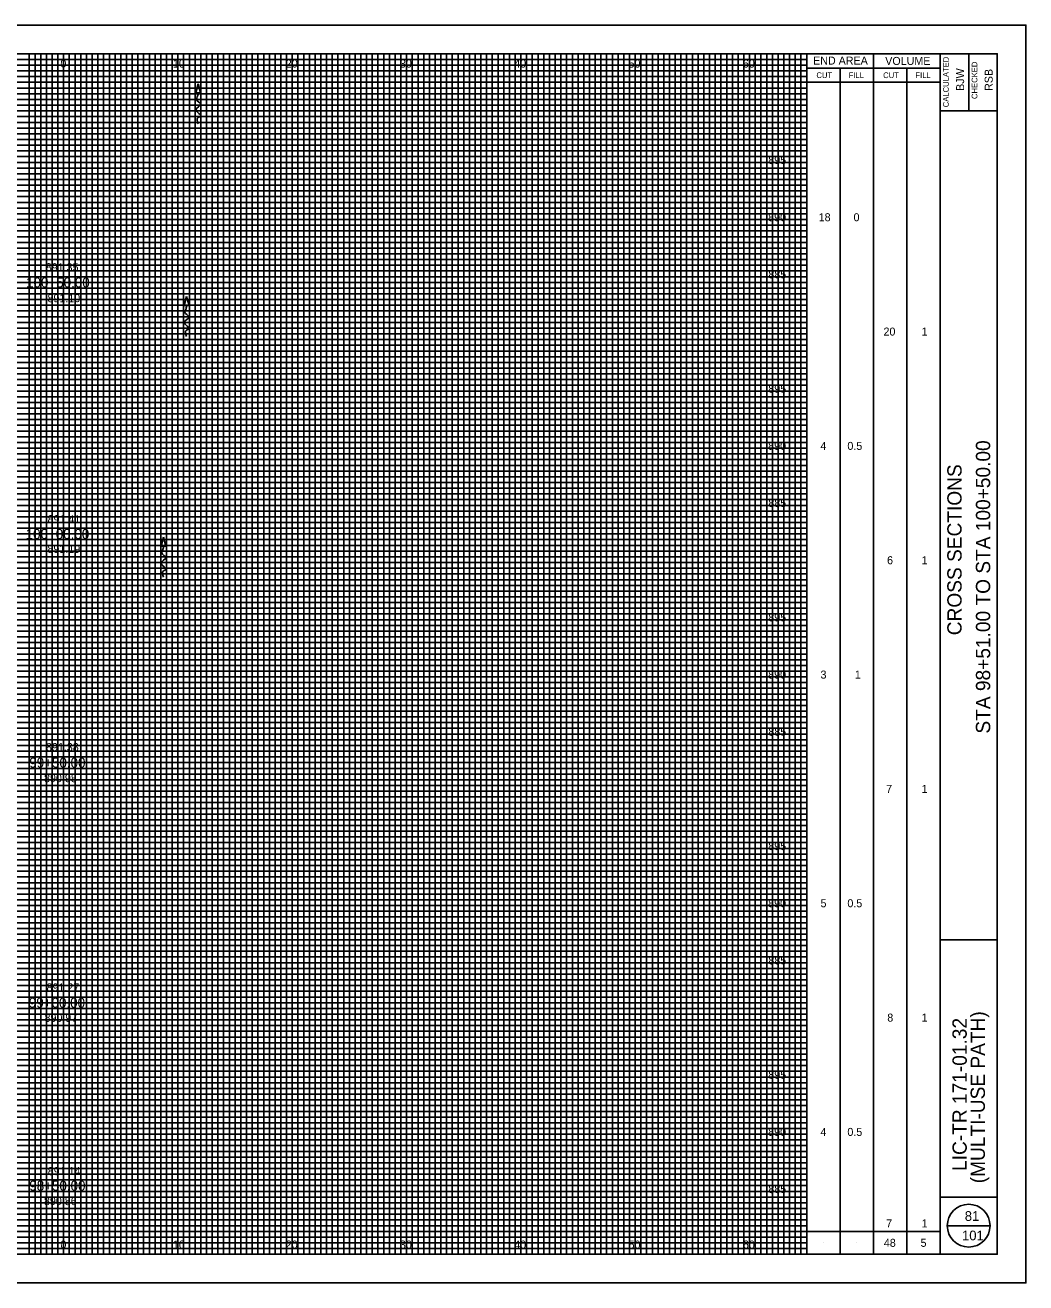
# Model space of a CAD drawing. Extents: x -10 to 160, y -2 to 3672.
# Drawn here: x 72.5 to 160, y 1377.5 to 1487.5 of the extents above; entities that cross this region are included whole.
import ezdxf

# ---------------------------------------------------------------- set-up
doc = ezdxf.new("R2010")
doc.units = 0
for name, color, linetype in [('DR_P_Flow_Arrow', 7, 'Continuous'), ('SH_Border', 7, 'Continuous'), ('SH_Cut_Line', 7, 'Continuous'), ('SH_Data', 7, 'Continuous'), ('SH_Major_Grid_Line', 7, 'Continuous'), ('SH_Minor_Grid_Line', 7, 'Continuous'), ('SH_Text', 7, 'Continuous'), ('TX_P_10', 7, 'Continuous'), ('TX_X_10', 7, 'Continuous')]:
    doc.layers.add(name, color=color, linetype=linetype)

msp = doc.modelspace()

# ---------------------------------------------------------------- linework, layer by layer
at = {"layer": 'DR_P_Flow_Arrow'}
for p, q in [((87.39, 1481.58), (87.6, 1482.38)), ((87.6, 1482.38), (87.81, 1481.58)), ((87.81, 1481.58), (87.39, 1481.58)), ((86.37, 1462.98), (86.58, 1463.78)), ((86.58, 1463.78), (86.8, 1462.98)), ((86.8, 1462.98), (86.37, 1462.98)), ((84.35, 1441.92), (84.56, 1442.72)), ((84.56, 1442.72), (84.78, 1441.92)), ((84.78, 1441.92), (84.35, 1441.92))]:
    msp.add_line(p, q, dxfattribs=at)
for points in [[(87.6, 1481.58), (87.6, 1481.55), (87.52, 1481.22), (87.45, 1481.01), (87.82, 1480.58), (87.41, 1480.1), (87.82, 1479.54), (87.59, 1479.43), (87.6, 1478.88)], [(86.58, 1462.98), (86.58, 1462.95), (86.51, 1462.62), (86.43, 1462.41), (86.8, 1461.99), (86.39, 1461.5), (86.8, 1460.94), (86.58, 1460.83), (86.58, 1460.28)], [(84.56, 1441.92), (84.56, 1441.89), (84.49, 1441.56), (84.41, 1441.35), (84.78, 1440.93), (84.37, 1440.44), (84.78, 1439.88), (84.56, 1439.77), (84.56, 1439.22)]]:
    msp.add_spline(points, degree=3, dxfattribs=at)
at = {"layer": 'SH_Border'}
for p, q in [((152.5, 1380), (152.5, 1485)), ((155, 1485), (155, 1480)), ((152.5, 1480), (157.5, 1480)), ((152.5, 1407.5), (157.5, 1407.5)), ((152.5, 1385), (157.5, 1385))]:
    msp.add_line(p, q, dxfattribs=at)
msp.add_lwpolyline([(0, 1485), (157.5, 1485), (157.5, 1380), (0, 1380)], close=True, dxfattribs=at)
at = {"layer": 'SH_Cut_Line'}
msp.add_lwpolyline([(-10, 1377.5), (160, 1377.5), (160, 1487.5), (-10, 1487.5)], close=True, dxfattribs=at)
at = {"layer": 'SH_Data'}
for p, q in [((140.83, 1380), (140.83, 1485)), ((146.67, 1380), (146.67, 1485)), ((140.83, 1483.75), (152.5, 1483.75)), ((143.75, 1380), (143.75, 1483.75)), ((149.58, 1380), (149.58, 1483.75)), ((140.83, 1482.5), (152.5, 1482.5)), ((140.83, 1382), (152.5, 1382)), ((153.12, 1382.5), (156.88, 1382.5)), ((142.29, 1381), (142.29, 1381)), ((145.21, 1381), (145.21, 1381)), ((148.12, 1381), (148.12, 1381)), ((151.04, 1381), (151.04, 1381))]:
    msp.add_line(p, q, dxfattribs=at)
msp.add_circle((155, 1382.5), 1.87, dxfattribs=at)
at = {"layer": 'SH_Major_Grid_Line'}
for p, q in [((75.83, 1380), (75.83, 1485)), ((80.83, 1380), (80.83, 1485)), ((85.83, 1380), (85.83, 1485)), ((90.83, 1380), (90.83, 1485)), ((95.83, 1380), (95.83, 1485)), ((100.83, 1380), (100.83, 1485)), ((105.83, 1380), (105.83, 1485)), ((110.83, 1380), (110.83, 1485)), ((115.83, 1380), (115.83, 1485)), ((120.83, 1380), (120.83, 1485)), ((125.83, 1380), (125.83, 1485)), ((130.83, 1380), (130.83, 1485)), ((135.83, 1380), (135.83, 1485)), ((5.83, 1480), (140.83, 1480)), ((5.83, 1475), (140.83, 1475)), ((5.83, 1470), (140.83, 1470)), ((5.83, 1465), (140.83, 1465)), ((5.83, 1460), (140.83, 1460)), ((5.83, 1455), (140.83, 1455)), ((5.83, 1450), (140.83, 1450)), ((5.83, 1445), (140.83, 1445)), ((5.83, 1440), (140.83, 1440)), ((5.83, 1435), (140.83, 1435)), ((5.83, 1430), (140.83, 1430)), ((5.83, 1425), (140.83, 1425)), ((5.83, 1420), (140.83, 1420)), ((5.83, 1415), (140.83, 1415)), ((5.83, 1410), (140.83, 1410)), ((5.83, 1405), (140.83, 1405)), ((5.83, 1400), (140.83, 1400)), ((5.83, 1395), (140.83, 1395)), ((5.83, 1390), (140.83, 1390)), ((5.83, 1385), (140.83, 1385))]:
    msp.add_line(p, q, dxfattribs=at)
at = {"layer": 'SH_Minor_Grid_Line'}
for p, q in [((72.83, 1380), (72.83, 1485)), ((73.33, 1380), (73.33, 1485)), ((73.83, 1380), (73.83, 1485)), ((74.33, 1380), (74.33, 1485)), ((74.83, 1380), (74.83, 1485)), ((75.33, 1380), (75.33, 1485)), ((76.33, 1380), (76.33, 1485)), ((76.83, 1380), (76.83, 1485)), ((77.33, 1380), (77.33, 1485)), ((77.83, 1380), (77.83, 1485)), ((78.33, 1380), (78.33, 1485)), ((78.83, 1380), (78.83, 1485)), ((79.33, 1380), (79.33, 1485)), ((79.83, 1380), (79.83, 1485)), ((80.33, 1380), (80.33, 1485)), ((81.33, 1380), (81.33, 1485)), ((81.83, 1380), (81.83, 1485)), ((82.33, 1380), (82.33, 1485)), ((82.83, 1380), (82.83, 1485)), ((83.33, 1380), (83.33, 1485)), ((83.83, 1380), (83.83, 1485)), ((84.33, 1380), (84.33, 1485)), ((84.83, 1380), (84.83, 1485)), ((85.33, 1380), (85.33, 1485)), ((86.33, 1380), (86.33, 1485)), ((86.83, 1380), (86.83, 1485)), ((87.33, 1380), (87.33, 1485)), ((87.83, 1380), (87.83, 1485)), ((88.33, 1380), (88.33, 1485)), ((88.83, 1380), (88.83, 1485)), ((89.33, 1380), (89.33, 1485)), ((89.83, 1380), (89.83, 1485)), ((90.33, 1380), (90.33, 1485)), ((91.33, 1380), (91.33, 1485)), ((91.83, 1380), (91.83, 1485)), ((92.33, 1380), (92.33, 1485)), ((92.83, 1380), (92.83, 1485)), ((93.33, 1380), (93.33, 1485)), ((93.83, 1380), (93.83, 1485)), ((94.33, 1380), (94.33, 1485)), ((94.83, 1380), (94.83, 1485)), ((95.33, 1380), (95.33, 1485)), ((96.33, 1380), (96.33, 1485)), ((96.83, 1380), (96.83, 1485)), ((97.33, 1380), (97.33, 1485)), ((97.83, 1380), (97.83, 1485)), ((98.33, 1380), (98.33, 1485)), ((98.83, 1380), (98.83, 1485)), ((99.33, 1380), (99.33, 1485)), ((99.83, 1380), (99.83, 1485)), ((100.33, 1380), (100.33, 1485)), ((101.33, 1380), (101.33, 1485)), ((101.83, 1380), (101.83, 1485)), ((102.33, 1380), (102.33, 1485)), ((102.83, 1380), (102.83, 1485)), ((103.33, 1380), (103.33, 1485)), ((103.83, 1380), (103.83, 1485)), ((104.33, 1380), (104.33, 1485)), ((104.83, 1380), (104.83, 1485)), ((105.33, 1380), (105.33, 1485)), ((106.33, 1380), (106.33, 1485)), ((106.83, 1380), (106.83, 1485)), ((107.33, 1380), (107.33, 1485)), ((107.83, 1380), (107.83, 1485)), ((108.33, 1380), (108.33, 1485)), ((108.83, 1380), (108.83, 1485)), ((109.33, 1380), (109.33, 1485)), ((109.83, 1380), (109.83, 1485)), ((110.33, 1380), (110.33, 1485)), ((111.33, 1380), (111.33, 1485)), ((111.83, 1380), (111.83, 1485)), ((112.33, 1380), (112.33, 1485)), ((112.83, 1380), (112.83, 1485)), ((113.33, 1380), (113.33, 1485)), ((113.83, 1380), (113.83, 1485)), ((114.33, 1380), (114.33, 1485)), ((114.83, 1380), (114.83, 1485)), ((115.33, 1380), (115.33, 1485)), ((116.33, 1380), (116.33, 1485)), ((116.83, 1380), (116.83, 1485)), ((117.33, 1380), (117.33, 1485)), ((117.83, 1380), (117.83, 1485)), ((118.33, 1380), (118.33, 1485)), ((118.83, 1380), (118.83, 1485)), ((119.33, 1380), (119.33, 1485)), ((119.83, 1380), (119.83, 1485)), ((120.33, 1380), (120.33, 1485)), ((121.33, 1380), (121.33, 1485)), ((121.83, 1380), (121.83, 1485)), ((122.33, 1380), (122.33, 1485)), ((122.83, 1380), (122.83, 1485)), ((123.33, 1380), (123.33, 1485)), ((123.83, 1380), (123.83, 1485)), ((124.33, 1380), (124.33, 1485)), ((124.83, 1380), (124.83, 1485)), ((125.33, 1380), (125.33, 1485)), ((126.33, 1380), (126.33, 1485)), ((126.83, 1380), (126.83, 1485)), ((127.33, 1380), (127.33, 1485)), ((127.83, 1380), (127.83, 1485)), ((128.33, 1380), (128.33, 1485)), ((128.83, 1380), (128.83, 1485)), ((129.33, 1380), (129.33, 1485)), ((129.83, 1380), (129.83, 1485)), ((130.33, 1380), (130.33, 1485)), ((131.33, 1380), (131.33, 1485)), ((131.83, 1380), (131.83, 1485)), ((132.33, 1380), (132.33, 1485)), ((132.83, 1380), (132.83, 1485)), ((133.33, 1380), (133.33, 1485)), ((133.83, 1380), (133.83, 1485)), ((134.33, 1380), (134.33, 1485)), ((134.83, 1380), (134.83, 1485)), ((135.33, 1380), (135.33, 1485)), ((136.33, 1380), (136.33, 1485)), ((136.83, 1380), (136.83, 1485)), ((137.33, 1380), (137.33, 1485)), ((137.83, 1380), (137.83, 1485)), ((138.33, 1380), (138.33, 1485)), ((138.83, 1380), (138.83, 1485)), ((139.33, 1380), (139.33, 1485)), ((139.83, 1380), (139.83, 1485)), ((140.33, 1380), (140.33, 1485)), ((5.83, 1484.5), (140.83, 1484.5)), ((5.83, 1484), (140.83, 1484)), ((5.83, 1483.5), (140.83, 1483.5)), ((5.83, 1483), (140.83, 1483)), ((5.83, 1482.5), (140.83, 1482.5)), ((5.83, 1482), (140.83, 1482)), ((5.83, 1481.5), (140.83, 1481.5)), ((5.83, 1481), (140.83, 1481)), ((5.83, 1480.5), (140.83, 1480.5)), ((5.83, 1479.5), (140.83, 1479.5)), ((5.83, 1479), (140.83, 1479)), ((5.83, 1478.5), (140.83, 1478.5)), ((5.83, 1478), (140.83, 1478)), ((5.83, 1477.5), (140.83, 1477.5)), ((5.83, 1477), (140.83, 1477)), ((5.83, 1476.5), (140.83, 1476.5)), ((5.83, 1476), (140.83, 1476)), ((5.83, 1475.5), (140.83, 1475.5)), ((5.83, 1474.5), (140.83, 1474.5)), ((5.83, 1474), (140.83, 1474)), ((5.83, 1473.5), (140.83, 1473.5)), ((5.83, 1473), (140.83, 1473)), ((5.83, 1472.5), (140.83, 1472.5)), ((5.83, 1472), (140.83, 1472)), ((5.83, 1471.5), (140.83, 1471.5)), ((5.83, 1471), (140.83, 1471)), ((5.83, 1470.5), (140.83, 1470.5)), ((5.83, 1469.5), (140.83, 1469.5)), ((5.83, 1469), (140.83, 1469)), ((5.83, 1468.5), (140.83, 1468.5)), ((5.83, 1468), (140.83, 1468)), ((5.83, 1467.5), (140.83, 1467.5)), ((5.83, 1467), (140.83, 1467)), ((5.83, 1466.5), (140.83, 1466.5)), ((5.83, 1466), (140.83, 1466)), ((5.83, 1465.5), (140.83, 1465.5)), ((5.83, 1464.5), (140.83, 1464.5)), ((5.83, 1464), (140.83, 1464)), ((5.83, 1463.5), (140.83, 1463.5)), ((5.83, 1463), (140.83, 1463)), ((5.83, 1462.5), (140.83, 1462.5)), ((5.83, 1462), (140.83, 1462)), ((5.83, 1461.5), (140.83, 1461.5)), ((5.83, 1461), (140.83, 1461)), ((5.83, 1460.5), (140.83, 1460.5)), ((5.83, 1459.5), (140.83, 1459.5)), ((5.83, 1459), (140.83, 1459)), ((5.83, 1458.5), (140.83, 1458.5)), ((5.83, 1458), (140.83, 1458)), ((5.83, 1457.5), (140.83, 1457.5)), ((5.83, 1457), (140.83, 1457)), ((5.83, 1456.5), (140.83, 1456.5)), ((5.83, 1456), (140.83, 1456)), ((5.83, 1455.5), (140.83, 1455.5)), ((5.83, 1454.5), (140.83, 1454.5)), ((5.83, 1454), (140.83, 1454)), ((5.83, 1453.5), (140.83, 1453.5)), ((5.83, 1453), (140.83, 1453)), ((5.83, 1452.5), (140.83, 1452.5)), ((5.83, 1452), (140.83, 1452)), ((5.83, 1451.5), (140.83, 1451.5)), ((5.83, 1451), (140.83, 1451)), ((5.83, 1450.5), (140.83, 1450.5)), ((5.83, 1449.5), (140.83, 1449.5)), ((5.83, 1449), (140.83, 1449)), ((5.83, 1448.5), (140.83, 1448.5)), ((5.83, 1448), (140.83, 1448)), ((5.83, 1447.5), (140.83, 1447.5)), ((5.83, 1447), (140.83, 1447)), ((5.83, 1446.5), (140.83, 1446.5)), ((5.83, 1446), (140.83, 1446)), ((5.83, 1445.5), (140.83, 1445.5)), ((5.83, 1444.5), (140.83, 1444.5)), ((5.83, 1444), (140.83, 1444)), ((5.83, 1443.5), (140.83, 1443.5)), ((5.83, 1443), (140.83, 1443)), ((5.83, 1442.5), (140.83, 1442.5)), ((5.83, 1442), (140.83, 1442)), ((5.83, 1441.5), (140.83, 1441.5)), ((5.83, 1441), (140.83, 1441)), ((5.83, 1440.5), (140.83, 1440.5)), ((5.83, 1439.5), (140.83, 1439.5)), ((5.83, 1439), (140.83, 1439)), ((5.83, 1438.5), (140.83, 1438.5)), ((5.83, 1438), (140.83, 1438)), ((5.83, 1437.5), (140.83, 1437.5)), ((5.83, 1437), (140.83, 1437)), ((5.83, 1436.5), (140.83, 1436.5)), ((5.83, 1436), (140.83, 1436)), ((5.83, 1435.5), (140.83, 1435.5)), ((5.83, 1434.5), (140.83, 1434.5)), ((5.83, 1434), (140.83, 1434)), ((5.83, 1433.5), (140.83, 1433.5)), ((5.83, 1433), (140.83, 1433)), ((5.83, 1432.5), (140.83, 1432.5)), ((5.83, 1432), (140.83, 1432)), ((5.83, 1431.5), (140.83, 1431.5)), ((5.83, 1431), (140.83, 1431)), ((5.83, 1430.5), (140.83, 1430.5)), ((5.83, 1429.5), (140.83, 1429.5)), ((5.83, 1429), (140.83, 1429)), ((5.83, 1428.5), (140.83, 1428.5)), ((5.83, 1428), (140.83, 1428)), ((5.83, 1427.5), (140.83, 1427.5)), ((5.83, 1427), (140.83, 1427)), ((5.83, 1426.5), (140.83, 1426.5)), ((5.83, 1426), (140.83, 1426)), ((5.83, 1425.5), (140.83, 1425.5)), ((5.83, 1424.5), (140.83, 1424.5)), ((5.83, 1424), (140.83, 1424)), ((5.83, 1423.5), (140.83, 1423.5)), ((5.83, 1423), (140.83, 1423)), ((5.83, 1422.5), (140.83, 1422.5)), ((5.83, 1422), (140.83, 1422)), ((5.83, 1421.5), (140.83, 1421.5)), ((5.83, 1421), (140.83, 1421)), ((5.83, 1420.5), (140.83, 1420.5)), ((5.83, 1419.5), (140.83, 1419.5)), ((5.83, 1419), (140.83, 1419)), ((5.83, 1418.5), (140.83, 1418.5)), ((5.83, 1418), (140.83, 1418)), ((5.83, 1417.5), (140.83, 1417.5)), ((5.83, 1417), (140.83, 1417)), ((5.83, 1416.5), (140.83, 1416.5)), ((5.83, 1416), (140.83, 1416)), ((5.83, 1415.5), (140.83, 1415.5)), ((5.83, 1414.5), (140.83, 1414.5)), ((5.83, 1414), (140.83, 1414)), ((5.83, 1413.5), (140.83, 1413.5)), ((5.83, 1413), (140.83, 1413)), ((5.83, 1412.5), (140.83, 1412.5)), ((5.83, 1412), (140.83, 1412)), ((5.83, 1411.5), (140.83, 1411.5)), ((5.83, 1411), (140.83, 1411)), ((5.83, 1410.5), (140.83, 1410.5)), ((5.83, 1409.5), (140.83, 1409.5)), ((5.83, 1409), (140.83, 1409)), ((5.83, 1408.5), (140.83, 1408.5)), ((5.83, 1408), (140.83, 1408)), ((5.83, 1407.5), (140.83, 1407.5)), ((5.83, 1407), (140.83, 1407)), ((5.83, 1406.5), (140.83, 1406.5)), ((5.83, 1406), (140.83, 1406)), ((5.83, 1405.5), (140.83, 1405.5)), ((5.83, 1404.5), (140.83, 1404.5)), ((5.83, 1404), (140.83, 1404)), ((5.83, 1403.5), (140.83, 1403.5)), ((5.83, 1403), (140.83, 1403)), ((5.83, 1402.5), (140.83, 1402.5)), ((5.83, 1402), (140.83, 1402)), ((5.83, 1401.5), (140.83, 1401.5)), ((5.83, 1401), (140.83, 1401)), ((5.83, 1400.5), (140.83, 1400.5)), ((5.83, 1399.5), (140.83, 1399.5)), ((5.83, 1399), (140.83, 1399)), ((5.83, 1398.5), (140.83, 1398.5)), ((5.83, 1398), (140.83, 1398)), ((5.83, 1397.5), (140.83, 1397.5)), ((5.83, 1397), (140.83, 1397)), ((5.83, 1396.5), (140.83, 1396.5)), ((5.83, 1396), (140.83, 1396)), ((5.83, 1395.5), (140.83, 1395.5)), ((5.83, 1394.5), (140.83, 1394.5)), ((5.83, 1394), (140.83, 1394)), ((5.83, 1393.5), (140.83, 1393.5)), ((5.83, 1393), (140.83, 1393)), ((5.83, 1392.5), (140.83, 1392.5)), ((5.83, 1392), (140.83, 1392)), ((5.83, 1391.5), (140.83, 1391.5)), ((5.83, 1391), (140.83, 1391)), ((5.83, 1390.5), (140.83, 1390.5)), ((5.83, 1389.5), (140.83, 1389.5)), ((5.83, 1389), (140.83, 1389)), ((5.83, 1388.5), (140.83, 1388.5)), ((5.83, 1388), (140.83, 1388)), ((5.83, 1387.5), (140.83, 1387.5)), ((5.83, 1387), (140.83, 1387)), ((5.83, 1386.5), (140.83, 1386.5)), ((5.83, 1386), (140.83, 1386)), ((5.83, 1385.5), (140.83, 1385.5)), ((5.83, 1384.5), (140.83, 1384.5)), ((5.83, 1384), (140.83, 1384)), ((5.83, 1383.5), (140.83, 1383.5)), ((5.83, 1383), (140.83, 1383)), ((5.83, 1382.5), (140.83, 1382.5)), ((5.83, 1382), (140.83, 1382)), ((5.83, 1381.5), (140.83, 1381.5)), ((5.83, 1381), (140.83, 1381)), ((5.83, 1380.5), (140.83, 1380.5))]:
    msp.add_line(p, q, dxfattribs=at)

# ---------------------------------------------------------------- texts
at = {"layer": 'SH_Data'}
for s, height, p in [('END AREA', 0.7, (141.39, 1484.05)), ('VOLUME', 0.7, (147.7, 1484.02)), ('CUT', 0.5, (141.68, 1482.87)), ('FILL', 0.5, (144.5, 1482.87)), ('CUT', 0.5, (147.52, 1482.87)), ('FILL', 0.5, (150.34, 1482.87)), ('81', 0.85, (154.66, 1382.92)), ('101', 0.85, (154.42, 1381.22))]:
    msp.add_text(s, height=height, dxfattribs=at).set_placement(p)
for s, height, p in [('CALCULATED', 0.5, (153.26, 1480.32)), ('CHECKED', 0.5, (155.76, 1481.04)), ('BJW', 0.7, (154.6, 1481.75)), ('RSB', 0.7, (157.1, 1481.75)), ('STA 98+51.00 TO STA 100+50.00', 1.25, (156.88, 1425.54)), ('CROSS SECTIONS', 1.25, (154.38, 1434.14)), ('LIC-TR 171-01.32', 1.25, (154.83, 1387.29)), ('(MULTI-USE PATH)', 1.25, (156.42, 1386.21))]:
    msp.add_text(s, height=height, rotation=90, dxfattribs=at).set_placement(p)
at = {"layer": 'SH_Text'}
for s, height, p in [('0', 0.7, (75.55, 1483.79)), ('10', 0.7, (85.39, 1483.79)), ('20', 0.7, (95.26, 1483.79)), ('30', 0.7, (105.25, 1483.79)), ('40', 0.7, (115.25, 1483.79)), ('50', 0.7, (125.25, 1483.79)), ('60', 0.7, (135.25, 1483.79)), ('895', 0.7, (137.47, 1475.35)), ('890', 0.7, (137.46, 1470.35)), ('18', 0.7, (141.88, 1470.35)), ('0', 0.7, (144.93, 1470.35)), ('100+50.00', 0.875, (72.55, 1464.56)), ('885', 0.7, (137.48, 1465.35)), ('20', 0.7, (147.55, 1460.35)), ('1', 0.7, (150.88, 1460.35)), ('895', 0.7, (137.47, 1455.35)), ('890', 0.7, (137.46, 1450.35)), ('4', 0.7, (142.03, 1450.35)), ('0.5', 0.7, (144.39, 1450.35)), ('885', 0.7, (137.48, 1445.35)), ('100+00.00', 0.875, (72.51, 1442.56)), ('6', 0.7, (147.86, 1440.35)), ('1', 0.7, (150.88, 1440.35)), ('895', 0.7, (137.47, 1435.35)), ('890', 0.7, (137.46, 1430.35)), ('3', 0.7, (142.04, 1430.35)), ('1', 0.7, (145.04, 1430.35)), ('885', 0.7, (137.48, 1425.35)), ('99+50.00', 0.875, (72.83, 1422.56)), ('7', 0.7, (147.78, 1420.35)), ('1', 0.7, (150.88, 1420.35)), ('895', 0.7, (137.47, 1415.35)), ('890', 0.7, (137.46, 1410.35)), ('5', 0.7, (142.04, 1410.35)), ('0.5', 0.7, (144.39, 1410.35)), ('885', 0.7, (137.48, 1405.35)), ('99+00.00', 0.875, (72.79, 1401.56)), ('8', 0.7, (147.88, 1400.35)), ('1', 0.7, (150.88, 1400.35)), ('895', 0.7, (137.47, 1395.35)), ('890', 0.7, (137.46, 1390.35)), ('4', 0.7, (142.03, 1390.35)), ('0.5', 0.7, (144.39, 1390.35)), ('98+50.00', 0.875, (72.83, 1385.56)), ('885', 0.7, (137.48, 1385.35)), ('7', 0.7, (147.78, 1382.35)), ('1', 0.7, (150.88, 1382.35)), ('0', 0.7, (75.55, 1380.5)), ('10', 0.7, (85.39, 1380.5)), ('20', 0.7, (95.26, 1380.5)), ('30', 0.7, (105.25, 1380.5)), ('40', 0.7, (115.25, 1380.5)), ('50', 0.7, (125.25, 1380.5)), ('60', 0.7, (135.25, 1380.5)), ('48', 0.7, (147.58, 1380.65)), ('5', 0.7, (150.79, 1380.65))]:
    msp.add_text(s, height=height, dxfattribs=at).set_placement(p)
at = {"layer": 'TX_P_10'}
for s, p in [('891.35', (74.27, 1465.98)), ('891.41', (74.43, 1443.94)), ('891.38', (74.29, 1424.01)), ('891.27', (74.34, 1402.99)), ('891.14', (74.44, 1386.92))]:
    msp.add_text(s, height=0.7, dxfattribs=at).set_placement(p)
at = {"layer": 'TX_X_10'}
for s, p in [('891.10', (74.42, 1463.27)), ('891.19', (74.42, 1441.34)), ('890.98', (74.12, 1421.29)), ('890.97', (74.16, 1400.33)), ('890.86', (74.11, 1384.3))]:
    msp.add_text(s, height=0.7, dxfattribs=at).set_placement(p)

doc.saveas('drawing.dxf')
